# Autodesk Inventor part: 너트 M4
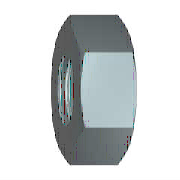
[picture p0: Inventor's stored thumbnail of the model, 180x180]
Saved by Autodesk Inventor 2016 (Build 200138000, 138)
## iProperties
Created: 2012-02
Part Number: 너트 M4
Material: 강철, 연강
Description: 6각 너트 및 6각 가는 너트 - 스타일 1
Document SubType Name: Modeling
Standard: KS B 1012
Designer: mduedu
Standards Organization: KS
Language: ko-KR
Size Designation: A M4
Categories: <MemberInstance><Categories><Category DisplayName="조임쇠" InternalName="e4da775c-781d-43d5-af7c-5136215cf5a6" Mnemonic="FSTN"><Category DisplayName="너트" InternalN
Density: 7.86 g/cm^3
Mass: 0.846697 g
Surface Area: 1.71448 cm^2
Volume: 0.107722 cm^3
Appearance: 강철
IsCustomPart: 0
Author: mduedu
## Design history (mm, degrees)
sketch "스케치1"
  geometry: L1 (-4.041, 0)-(-2.021, 3.5); L2 (-2.021, 3.5)-(2.021, 3.5); L3 (2.021, 3.5)-(4.041, 0); L4 (4.041, 0)-(2.021, -3.5); L5 (2.021, -3.5)-(-2.021, -3.5); L6 (-2.021, -3.5)-(-4.041, 0); 2 further points
  constraints: 12 end point, 1 coincident, 1 horizontal, 11 other
  dimensions: "d0" = 8.0829 distance of L3.end L1.start (= 1.1547 x SW)
extrude "본체" new body sketch "스케치1" distance "d1" = 3.2 (= KOH); taper "d2" = 0 deg
sketch "스케치2"
  geometry: L1 (0, 2.021)-(0, 4.041) reference; L2 (0, 4.041)-(3.2, 4.041) reference; L3 (3.2, 2.021)-(3.2, 4.041) reference; L4 (-0.64, 0)-(3.84, 0) reference; L5 (0.313, 4.041)-(0, 3.5); L6 (2.887, 4.041)-(3.2, 3.5)
  constraints: 4 end point, 4 point on line
  dimensions: "d3" = 30 deg angle of L1 L5 (= ANG1); "d4" = 30 deg angle of L3 L6 (= ANG2); "d5" = 7 diameter of L5.end L4 (= SW0); "d6" = 7 diameter of L6.end L4 (= SW01)
revolve "모따기1" sketch "스케치2" stored, may be unused: angle "d7" = 90 deg
sketch "스케치3"
  geometry: A1 r 3.5 centre (0, 0) between (-1.75, -3.031) and (1.75, -3.031) reference; 1 further point
  constraints: 1 coincident
hole "스레드" sketch "스케치3" at (0, 0) diameter "d25" = 3.242; stored, may be unused: countersink angle "d29" = 82 deg, drill point angle "d31" = 118 deg; dims "d26" = 6, "d27" = 4, "d28" = 2, "d30" = 8
workaxis "Work Axis1"
workplane "Work Plane1"
body "Solid1"
chamfer "모따기2" distance "d8" = 0.37889 (= -0.5 x GD1 + 0.5 x NND); stored, may be unused: angle "d9" = 30 deg, second distance "d40" = 0.37889 (= -0.5 x GD1 + 0.5 x NND)
chamfer "모따기3" distance "d10" = 0.37889 (= -0.5 x GD1 + 0.5 x NND); stored, may be unused: angle "d11" = 30 deg, second distance "d41" = 0.37889 (= -0.5 x GD1 + 0.5 x NND)
other parameters: "ANG1" = 30 deg [user parameter; used in 1 equation term], "ANG2" = 30 deg [user parameter; used in 1 equation term], "NND" = 4 [user parameter; used in 4 equation terms], "KOH" = 3.2 [user parameter; used in 1 equation term], "SW" = 7 [user parameter; used in 4 equation terms], "SW0" = 7 (= SW) [user parameter; used in 1 equation term], "SW01" = 7 (= SW) [user parameter; used in 1 equation term], "GD1" = 3.24223 (computed from THREADDIA, PTC, TOA) [user parameter; used in 4 equation terms], "d13" = 0, "d14" = 0, "d39" = 0, "d42" = 0, "GUL" = 0.37889 (= 0.541266 x PTC) [user parameter], "TPU" = 14.28571 (computed from PTC) [user parameter], "THREADDIA" = 4 [user parameter; used in 1 equation term], "TOA" = 30 deg [user parameter; used in 1 equation term], "PTC" = 0.7 [user parameter; used in 4 equation terms], "E0" = 8.085 (= 1.155 x SW) [user parameter], "GAL" = 0.37889 (= 0.541266 x PTC) [user parameter]
